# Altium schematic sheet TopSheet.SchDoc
size 431 x 279 mm; Date: Not shown in title block; ApprovedBy: Not shown in title block; CheckedBy: Not shown in title block; Author: Not shown in title block; CompanyName: Not shown in title block; Engineer: Not shown in title block; Organization: Not shown in title block; Address1: Not shown in title block; Address2: Not shown in title block; Address3: Not shown in title block; Address4: Not shown in title block; DocumentNumber: 1; Revision: Use project parameter SCH_Rev; SheetNumber: 1; SheetTotal: 4; PageSetup: Record=PageOptions¦CenterHorizontal=True¦CenterVertical=True¦PrintScale=1.00¦XCorrection=1.00¦YCorrection=1.00¦PrintKind=0¦BorderSize=5000000¦LeftOffset=0¦BottomOffset=0¦Orientation=2¦PaperLength=1000¦PaperWidth=1000¦Scale=100¦PaperSource=15¦PrintQuality=600¦MediaType=1¦DitherType=10¦PaperKind=Letter¦PrintScaleMode=1
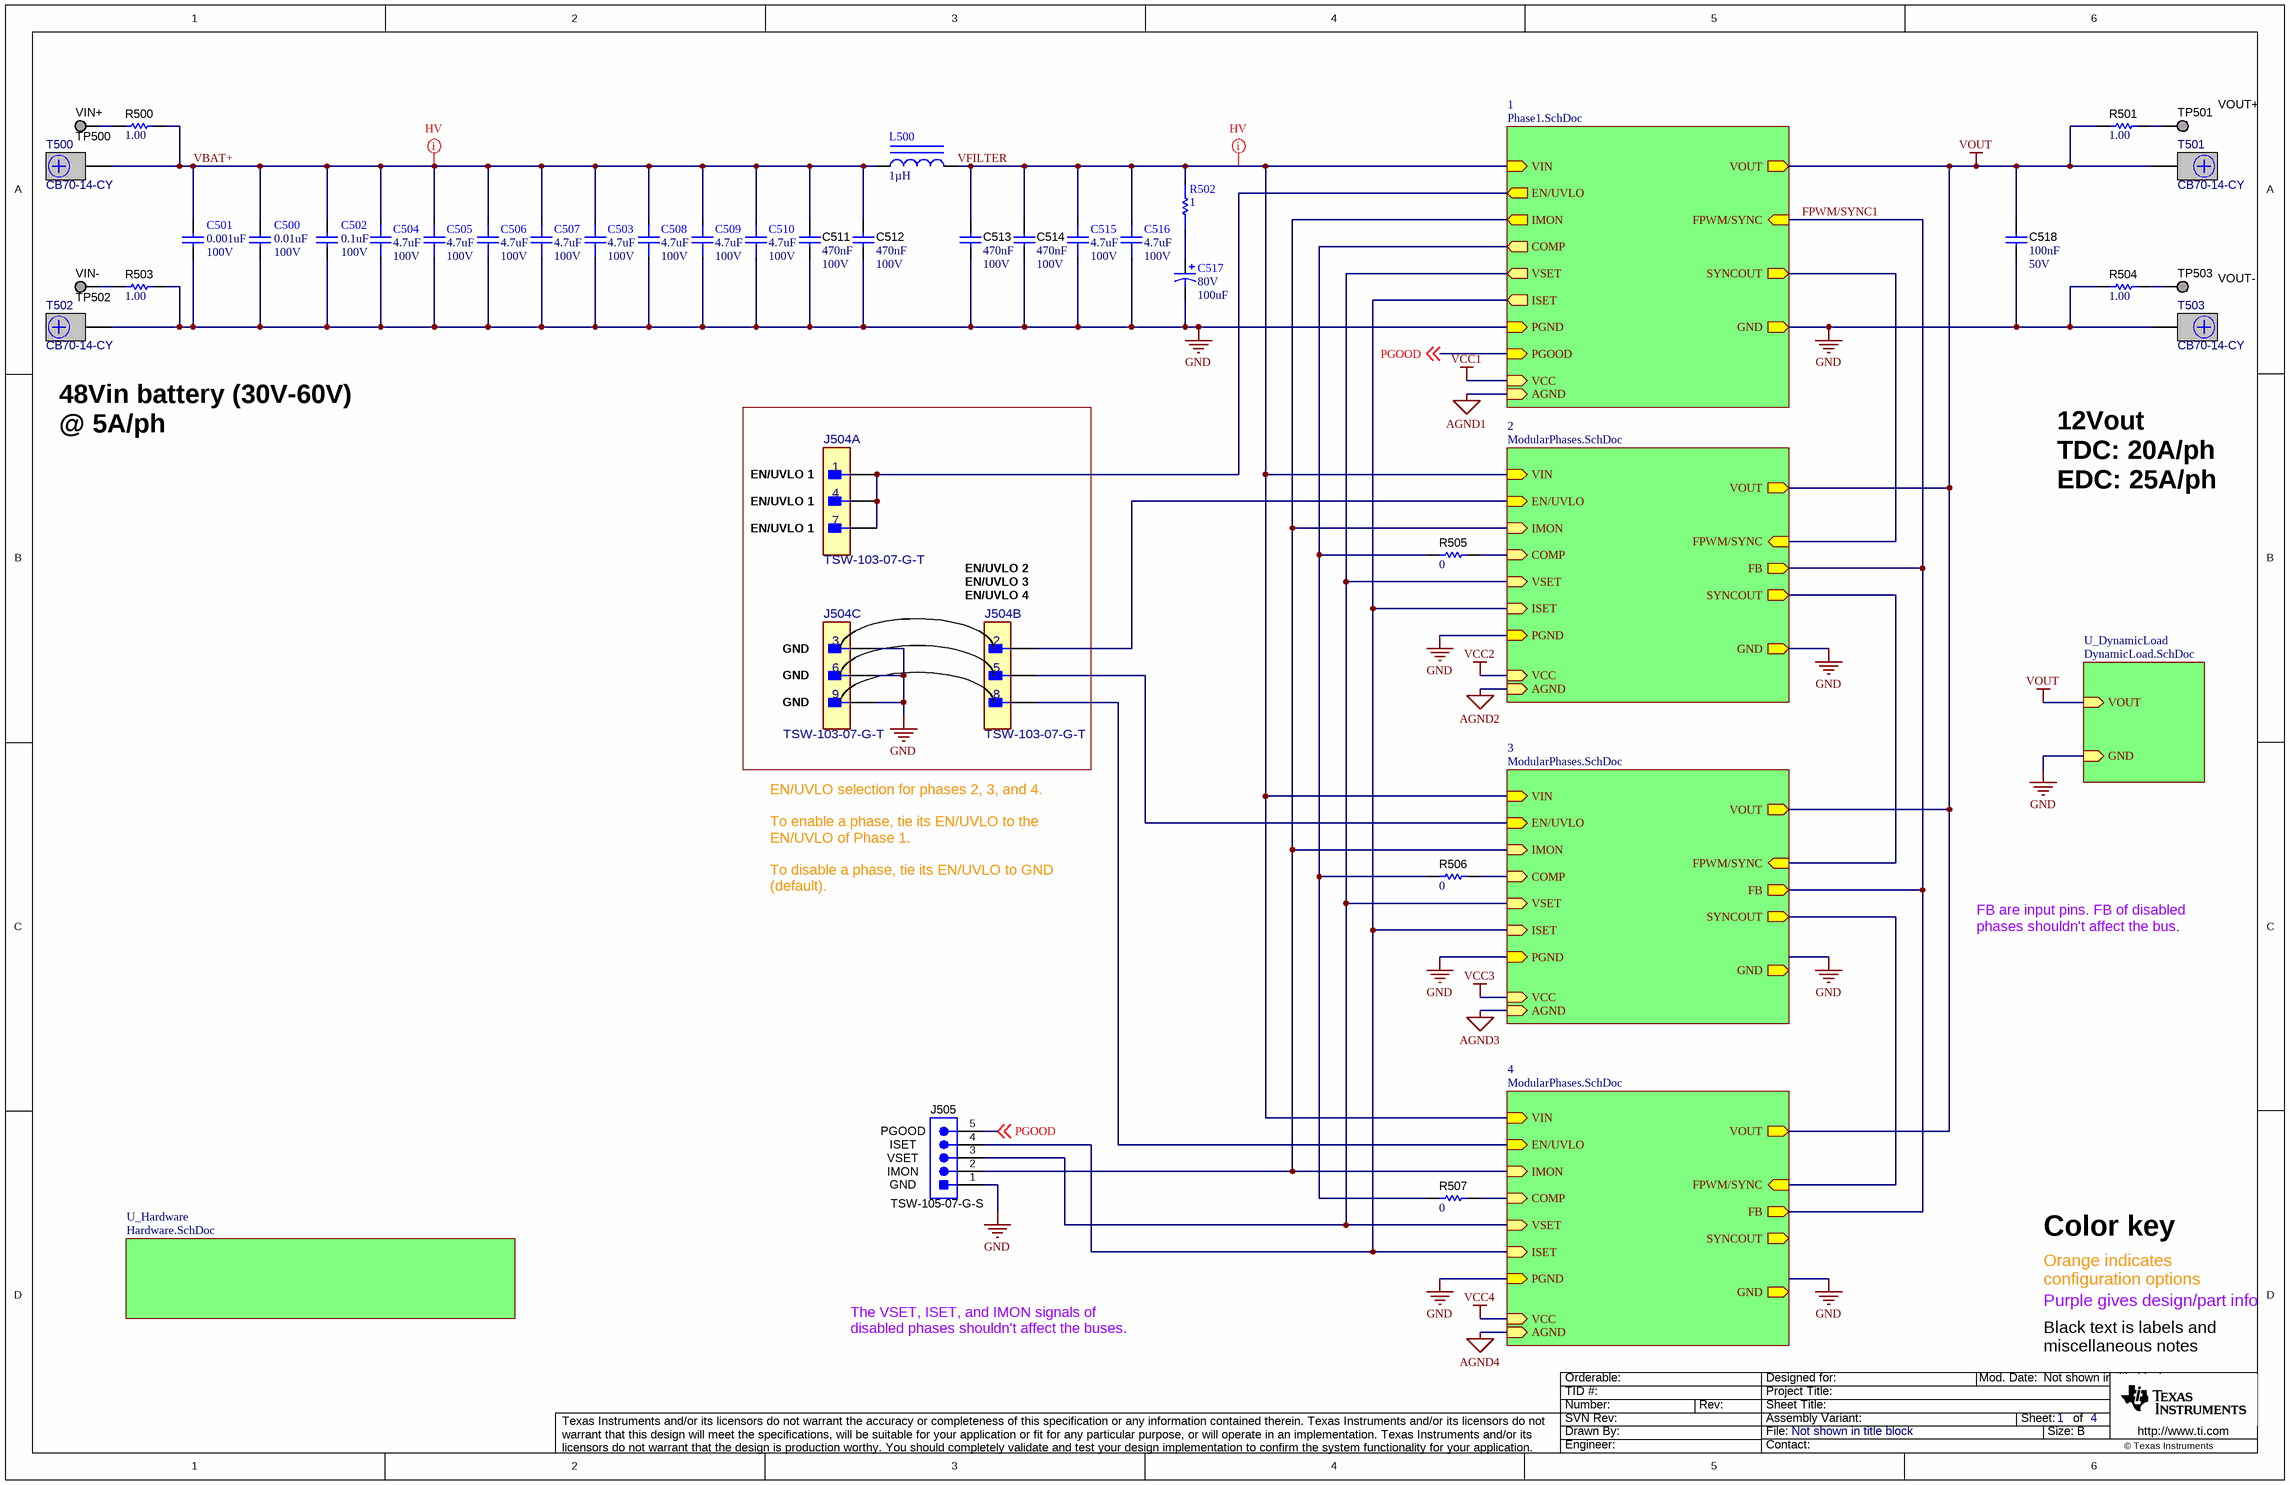
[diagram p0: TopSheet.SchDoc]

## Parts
C500  Value2: 100V  ValueDisplayed: 0.01uF  [0603L]  (hidden comment: GRM188R72A103KA01D)
C501  Cap_F: 0.001uF  VDC_V: 100V  [0603L]  (hidden comment: CGA3E2X7R2A102K080AA)
C502  Value2: 100V  ValueDisplayed: 0.1uF  [0805]  (hidden comment: C0805C104K1RACTU)
C503  ValueDisplayed: 4.7uF  VDC_V: 100V  [FP-GCJ32DC72A475KE01L_1210-MFG]  (hidden comment: GCJ32DC72A475KE01L)
C504  ValueDisplayed: 4.7uF  VDC_V: 100V  [FP-GCJ32DC72A475KE01L_1210-MFG]  (hidden comment: GCJ32DC72A475KE01L)
C505  ValueDisplayed: 4.7uF  VDC_V: 100V  [FP-GCJ32DC72A475KE01L_1210-MFG]  (hidden comment: GCJ32DC72A475KE01L)
C506  ValueDisplayed: 4.7uF  VDC_V: 100V  [FP-GCJ32DC72A475KE01L_1210-MFG]  (hidden comment: GCJ32DC72A475KE01L)
C507  ValueDisplayed: 4.7uF  VDC_V: 100V  [FP-GCJ32DC72A475KE01L_1210-MFG]  (hidden comment: GCJ32DC72A475KE01L)
C508  ValueDisplayed: 4.7uF  VDC_V: 100V  [FP-GCJ32DC72A475KE01L_1210-MFG]  (hidden comment: GCJ32DC72A475KE01L)
C509  ValueDisplayed: 4.7uF  VDC_V: 100V  [FP-GCJ32DC72A475KE01L_1210-MFG]  (hidden comment: GCJ32DC72A475KE01L)
C510  ValueDisplayed: 4.7uF  VDC_V: 100V  [FP-GCJ32DC72A475KE01L_1210-MFG]  (hidden comment: GCJ32DC72A475KE01L)
C511  Cap_F: 470nF  VDC_V: 100V  [0805L]  (hidden comment: GRM21BR72A474KA73L)
C512  Cap_F: 470nF  VDC_V: 100V  [0805L]  (hidden comment: GRM21BR72A474KA73L)
C513  Cap_F: 470nF  VDC_V: 100V  [0805L]  (hidden comment: GRM21BR72A474KA73L)
C514  Cap_F: 470nF  VDC_V: 100V  [0805L]  (hidden comment: GRM21BR72A474KA73L)
C515  ValueDisplayed: 4.7uF  VDC_V: 100V  [FP-GCJ32DC72A475KE01L_1210-MFG]  (hidden comment: GCJ32DC72A475KE01L)
C516  ValueDisplayed: 4.7uF  VDC_V: 100V  [FP-GCJ32DC72A475KE01L_1210-MFG]  (hidden comment: GCJ32DC72A475KE01L)
C517  VDC_V: 80V  ValueDisplayed: 100uF  [SM_RADIAL_H13]  (hidden comment: EEV-FK1K101Q)
C518  Cap_F: 100nF  VDC_V: 50V  [0603L]  (hidden comment: 06035C104KAZ2A)
J504  TSW-103-07-G-T  [FP-TSW-103-07-G-T_HDR9-MFG]  (parts A,B,C of 3)
J505  TSW-105-07-G-S  [TSW-105-07-X-S]
L500  ValueDisplayed: 1µH  [VCHA105D]  (hidden comment: VCHA105D-1R0MS6)
R500  ValueDisplayed: 1.00  [0603L]  (hidden comment: CRCW06031R00FKEA)
R501  ValueDisplayed: 1.00  [0603L]  (hidden comment: CRCW06031R00FKEA)
R502  value 1  [FP-RCL12251R00FKEG_2512-MFG]  (hidden comment: RCL12251R00FKEG)
R503  ValueDisplayed: 1.00  [0603L]  (hidden comment: CRCW06031R00FKEA)
R504  ValueDisplayed: 1.00  [0603L]  (hidden comment: CRCW06031R00FKEA)
R505  ValueDisplayed: 0  [0402L]  (hidden comment: RK73Z1ETTP)
R506  ValueDisplayed: 0  [0402L]  (hidden comment: RK73Z1ETTP)
R507  ValueDisplayed: 0  [0402L]  (hidden comment: RK73Z1ETTP)
T500  CB70-14-CY  [CB70-14-CY]
T501  CB70-14-CY  [CB70-14-CY]
T502  CB70-14-CY  [CB70-14-CY]
T503  CB70-14-CY  [CB70-14-CY]
TP500  VIN+  [Keystone_5019]
TP501  VOUT+  [Keystone_5019]
TP502  VIN-  [Keystone_5019]
TP503  VOUT-  [Keystone_5019]

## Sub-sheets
1 = Phase1.SchDoc: VIN (in), PGND (in), VOUT (out), GND (out), EN/UVLO (out), SYNCOUT (out), COMP (out), AGND (in), VCC (in), IMON (out), ISET (out), VSET (out), FPWM/SYNC (in), PGOOD (in)
2 = ModularPhases.SchDoc: VIN (in), PGND (in), VOUT (out), GND (out), FPWM/SYNC (in), SYNCOUT (out), COMP (in), AGND (in), VCC (in), EN/UVLO (in), IMON (in), VSET (in), ISET (in), FB (out)
3 = ModularPhases.SchDoc: VIN (in), PGND (in), VOUT (out), GND (out), FPWM/SYNC (in), SYNCOUT (out), COMP (in), AGND (in), VCC (in), EN/UVLO (in), IMON (in), VSET (in), ISET (in), FB (out)
4 = ModularPhases.SchDoc: VIN (in), PGND (in), VOUT (out), GND (out), FPWM/SYNC (in), SYNCOUT (out), COMP (in), AGND (in), VCC (in), EN/UVLO (in), IMON (in), VSET (in), ISET (in), FB (out)
U_DynamicLoad = DynamicLoad.SchDoc: VOUT (in), GND (in)
U_Hardware = Hardware.SchDoc: no entries

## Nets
GND: C500.1 C501.2 C502.2 C503.1 C504.1 C505.1 C506.1 C507.1 C508.1 C509.1 C510.1 C511.2 C512.2 C513.2 C514.2 C515.1 C516.1 C517.2(-) C518.2 J504.3 J504.6 J504.9 J505.1 R503.2 R504.1 T502.1 T503.1 ; sheet 2/PGND, sheet 2/GND, sheet 1/PGND, sheet 1/GND, sheet U_DynamicLoad/GND, sheet 3/PGND, sheet 4/PGND
VOUT: C518.1 R501.1 T501.1 ; sheet 2/VOUT, sheet 1/VOUT, sheet U_DynamicLoad/VOUT, sheet 3/VOUT, sheet 4/VOUT
FPWM/SYNC1: sheet 2/FB, sheet 1/FPWM/SYNC, sheet 3/FB, sheet 4/FB
PGOOD: J505.5 ; off-sheet PGOOD, sheet 1/PGOOD
VBAT+: C500.2 C501.1 C502.1 C503.2 C504.2 C505.2 C506.2 C507.2 C508.2 C509.2 C510.2 C511.1 C512.1 L500.1 R500.2 T500.1
VFILTER: C513.1 C514.1 C515.2 C516.2 L500.2 R502.2 ; sheet 2/VIN, sheet 1/VIN, sheet 3/VIN, sheet 4/VIN
NetC517_1: C517.1(+) R502.1
NetJ504_1: J504.1 J504.4 J504.7 ; sheet 1/EN/UVLO
NetJ504_2: J504.2 ; sheet 2/EN/UVLO
NetJ504_5: J504.5 ; sheet 3/EN/UVLO
NetJ504_8: J504.8 ; sheet 4/EN/UVLO
NetJ505_2: J505.2 ; sheet 2/IMON, sheet 1/IMON, sheet 3/IMON, sheet 4/IMON
NetJ505_3: J505.3 ; sheet 2/VSET, sheet 1/VSET, sheet 3/VSET, sheet 4/VSET
NetJ505_4: J505.4 ; sheet 2/ISET, sheet 1/ISET, sheet 3/ISET, sheet 4/ISET
NetR500_1: R500.1 TP500.1
NetR501_2: R501.2 TP501.1
NetR503_1: R503.1 TP502.1
NetR504_2: R504.2 TP503.1
NetR505_1: R505.1 ; sheet 2/COMP
NetR505_2: R505.2 R506.2 R507.2 ; sheet 1/COMP
NetR506_1: R506.1 ; sheet 3/COMP
NetR507_1: R507.1 ; sheet 4/COMP
(unnamed): sheet 2/FPWM/SYNC, sheet 1/SYNCOUT
(unnamed): sheet 2/SYNCOUT, sheet 3/FPWM/SYNC  [a separate net that carries the same name]
(unnamed): sheet 3/SYNCOUT, sheet 4/FPWM/SYNC  [a separate net that carries the same name]

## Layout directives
net class HV: VBAT+, VFILTER

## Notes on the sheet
- (near T502) 48Vin battery (30V-60V) @ 5A/ph
- (near J504) EN/UVLO 1
- 12Vout
  TDC: 20A/ph
  EDC: 25A/ph
- EN/UVLO 2
- EN/UVLO 3
- (near J504) EN/UVLO 4
- (near J504) GND
- EN/UVLO selection for phases 2, 3, and 4.
  To enable a phase, tie its EN/UVLO to the EN/UVLO of Phase 1.
  To disable a phase, tie its EN/UVLO to GND (default).
- FB are input pins. FB of disabled phases shouldn't affect the bus.
- (near J505) IMON
- (near J505) VSET
- (near J505) ISET
- (near J505) PGOOD
- (near J505) GND
- Orange indicates configuration options
- Color key
- The VSET, ISET, and IMON signals of disabled phases shouldn't affect the buses.
- Purple gives design/part info
- Black text is labels and miscellaneous notes

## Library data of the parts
C500 = CMP-0007468-5: CAP, CERM, 0.01 uF, 100 V, +/- 10%, X7R, 0603; Manufacturer: MuRata; TaMin_C: -55°C; Polarized: N; SizeAreaWB_mm2: 4.68; Value1: Unknown; U/M: EA; Value: 0.01uF; TaMax_C: 125°C; SizeZ_mm: 1; SizeX_mm: 1.6; SizeY_mm: 0.8; Cap_Case: 0603; SizeArea_mm2: 1.28; Cap_F: 10nF; AEC Category: Q200
C501 = CMP-0007081-4: CAP, CERM, 1000 pF, 100 V, +/- 10%, X7R, AEC-Q200 Grade 1, 0603; Manufacturer: TDK; TaMin_C: -55°C; ESR_ohm: 1.9714; Polarized: N; SizeAreaWB_mm2: 4.68; Value1: 1.97137 ohm; U/M: EA; Value: 1000pF; TaMax_C: 125°C; SizeZ_mm: 1; SizeX_mm: 1.6; SizeY_mm: 0.8; Cap_Case: 0603; SizeArea_mm2: 1.28; AEC Qualified: Y; IRMS_A: 305.705mA; AEC Category: Q200
C502 = CMP-0007722-2: CAP, CERM, 0.1 uF, 100 V, +/- 10%, X7R, 0805; Manufacturer: Kemet; TaMin_C: -55°C; ESR_ohm: 64m; Polarized: N; SizeAreaWB_mm2: 6.75; Value1: 0.064 ohm; U/M: EA; Value: 0.1uF; TaMax_C: 125°C; SizeZ_mm: 1.45; SizeX_mm: 2; SizeY_mm: 1.25; SizeArea_mm2: 2.5; Cap_F: 100nF; IRMS_A: 1.64A; AEC Category: Q200
C503-C510 C515 C516 = CMP-0093675-1: 4.7uF ±10% 100V Ceramic Capacitor X7S 1210 (3225 Metric); Manufacturer: Murata; Value: 4.7µF; AEC Qualified: Yes; TempCo: 22%; SizeZ_mm: 2.3mm; AEC Grade: Grade 1
C511-C514 = CMP-0008374-2: CAP, CERM, 0.47 uF, 100 V, +/- 10%, X7R, 0805; Manufacturer: MuRata; TaMin_C: -55°C; Polarized: N; SizeAreaWB_mm2: 6.75; Value1: Unknown; U/M: EA; Value: 0.47uF; TaMax_C: 125°C; SizeZ_mm: 1.45; SizeX_mm: 2; SizeY_mm: 1.25; Cap_Case: 0805; SizeArea_mm2: 2.5; AEC Category: Q200
C517 = CMP-0011216-2: CAP, AL, 100 uF, 80 V, +/- 20%, 0.32 ohm, AEC-Q200 Grade 2, SMD; Manufacturer: Panasonic; TaMin_C: -55°C; ESR_ohm: 0.32; Polarized: Y; SizeAreaWB_mm2: 263.5; U/M: EA; Value: 100uF; TaMax_C: 105°C; SizeZ_mm: 13.5; SizeX_mm: 15; Cap_Case: H13; SizeArea_mm2: 202.5; CompType: Capacitor; Cap_F: 100µF; IRMS_A: 500mA; AEC Grade: 2; AEC Category: Q200
C518 = CMP-0079095-1: CAP, CERM, 0.1 µF, 50 V,+/- 10%, X7R, AEC-Q200 Grade 1, 0603; Manufacturer: AVX; SizeAreaWB_mm2: 4.68; SizeArea_mm2: 1.28; AEC Qualified: Y; AEC Category: Q200; Value: 0.1uF; TaMax_C: 125°C; SizeZ_mm: 1; Polarized: N; TaMin_C: -55°C; SizeY_mm: 0.8; U/M: EA; SizeX_mm: 1.6; Cap_Case: 0603; ValueDisplayed: 0.1µF
J504 = CMP-0090263-1: Connector Header Through Hole 9 position 0.100" (2.54mm); Manufacturer: Samtec; Conn Gender: Male; AEC Qualified: No; Conn Orientation: Straight; Row_Count: 3; SizeZ_mm: 8.64mm; ContactFinish: Gold,Nickel
J505 = CMP-0075411-1: Header, 100mil, 5x1, Gold, TH; Manufacturer: Samtec; Pitch_mm: 2.54; Cert_VDE: N; Gender: Male; Cert_CSA: Y; Voltage_V: 550V; Green_REACh: Passed; Current_A: 6.3A; CT: False; Green_Lifecycle: Active; Row_Count: 1; CNHeader: True
L500 = CMP-0086238-1: Inductor, 1 µH, 30 A, 0.00276 ohm, AEC-Q200 Grade 0, SMD; Manufacturer: Cyntec; AEC Category: Q200; AEC Grade: 0; Value: 1uH; AEC Qualified: Y; Irms: 30A @ 40C rise; Isat: 37A @ 30% inductance drop; DCR_ohm: 2.76m; SizeX_mm: 10.85; Imax_A: 30A; SizeArea_mm2: 108.5; SizeZ_mm: 5.4; SizeAreaWB_mm2: 154.2; SizeY_mm: 10
R500 R501 R503 R504 = CMP-0022170-4: RES, 1.00, 1%, 0.1 W, AEC-Q200 Grade 0, 0603; Manufacturer: Vishay-Dale; Power_W: 100mW; TempCo: 100 ppm/C; Value_Code: 1R00; Value: 1.00; EIA_Code: E96; Res_ohm: 1; SizeX_mm: 1.6; SizeY_mm: 0.8; Value2: 0.1W; SizeArea_mm2: 1.28; AEC Qualified: Y; VDC_V: 75V; AEC Category: Q200; AEC Grade: 0
R502 = CMP-0084352-2: 1 Ohms ±1% 2W Chip Resistor Wide 2512 (6432 Metric), 1225 Automotive AEC-Q200 Thick Film; Manufacturer: Vishay Dale; SizeZ_mm: 0.8mm; Symbol Name: SYM-RCL12251R00FKEG; TempCo: 100ppm/°C; VDC_V: 200V; AEC Qualified: Yes; AEC Grade: Grade 0
R505-R507 = CMP-0027007-2: RES, 0, 5%, 0.063 W, AEC-Q200 Grade 0, 0402; Manufacturer: KOA Speer; Power_W: 63mW; TempCo: ppm/C; Value_Code: 0000; U/M: EA; Value: 0; EIA_Code: E24; SizeX_mm: 1; SizeY_mm: 0.5; SizeZ_mm: 0.6; Value2: 0.063W; AEC Qualified: Y; AEC Category: Q200
T500-T503 = CMP-0055443-2: Terminal 90A Lug; Manufacturer: Panduit; Green_Lifecycle: Not Set; Cert_CULUS: Y; Green_REACh: Incomplete; Voltage_V: 600V; CompType: Screw Terminal; ContactFinish: Copper
TP500-TP503 = CMP-0055162-1: Test Point, Miniature, SMT; Manufacturer: Keystone; PartNumber: 5019; CNHeader: FALSE; Green_Lifecycle: Active; Green_REACh: Passed; CT: TRUE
